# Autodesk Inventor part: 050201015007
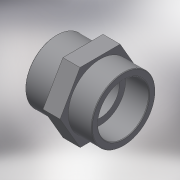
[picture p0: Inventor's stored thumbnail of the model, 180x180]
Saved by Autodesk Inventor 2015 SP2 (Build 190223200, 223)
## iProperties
Created: 2017-10
Part Number: 050201015007
Material: Generic
Description: PLASSON THREADED REDUCER PVC 1.1/2"-3/4"F
Document SubType Name: Modeling
Designer: KIM
Density: 1 g/cm^3
Appearance: Default
Author: KIM
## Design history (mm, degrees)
derived "050201.ipt"
feature "Solid1::050201.ipt"
tag "TaggingFeature1"
body "Solid1"
other parameters: "d0" = 54, "d1" = 24.117, "d4" = 19.2936, "d5" = 22, "d6" = 18, "d8" = 47.803, "d10" = 18, "d13" = 0, "d14" = 0.47803, "d15" = 16, "d16" = 38.2424, "d17" = 36.1755, "R_" = 47.803, "B_" = 16, "lt_" = 18, "H_" = 54, "G_" = 24.117, "lt_1" = 22
